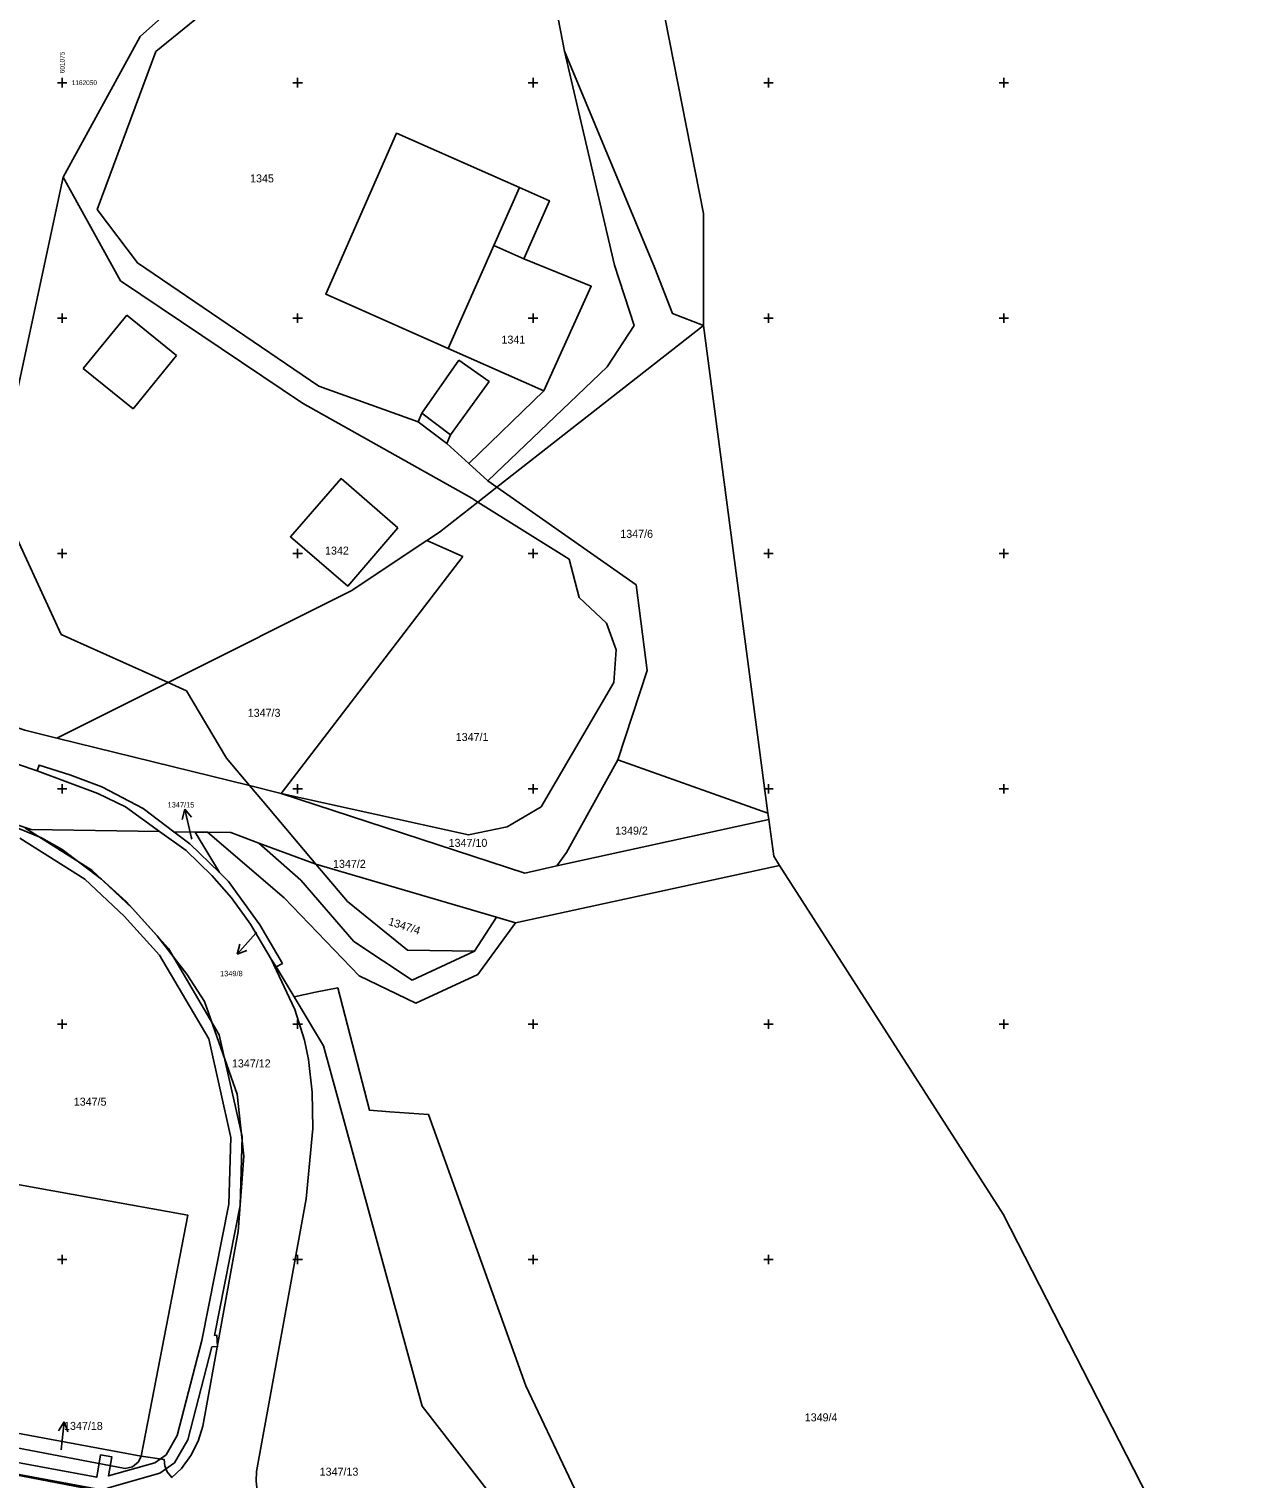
# Model space of a CAD drawing. Extents: x -601602 to -600882, y -1162594 to -1161950.
# Drawn here: x -601078.5 to -600948.1, y -1162198.3 to -1162044.3 of the extents above; entities that cross this region are included whole.
import ezdxf

# ---------------------------------------------------------------- set-up
doc = ezdxf.new("R2010")
doc.units = 0
for name, color, linetype in [('KN_Hranice parcel', 7, 'Continuous'), ('KN_Parcelní čísla', 7, 'Continuous'), ('KN_Pop  PČ popisy', 7, 'Continuous'), ('KN_Vnitřní kresba', 7, 'Continuous'), ('KN_Věcná břemena k části', 7, 'Continuous'), ('X_SOUR_KRIZKY_SEVER', 7, 'Continuous')]:
    doc.layers.add(name, color=color, linetype=linetype)

# ---------------------------------------------------------------- blocks, each defined once
blk = doc.blocks.new('1029_45')
at = {"layer": 'KN_Pop  PČ popisy'}
for p, q in [((0, 0), (-2.01, -2.23)), ((-2.01, -2.23), (-1.71, -1.15)), ((-2.01, -2.23), (-0.97, -1.82))]:
    blk.add_line(p, q, dxfattribs=at)
blk = doc.blocks.new('1029_48')
at = {"layer": 'KN_Pop  PČ popisy'}
for p, q in [((0.31, 2.98), (-0.29, 2.04)), ((0, 0), (0.31, 2.98)), ((0.31, 2.98), (0.71, 1.94))]:
    blk.add_line(p, q, dxfattribs=at)
blk = doc.blocks.new('1029_49')
at = {"layer": 'KN_Pop  PČ popisy'}
for p, q in [((-0.67, 2.92), (-0.94, 1.84)), ((0, 0), (-0.67, 2.92)), ((-0.67, 2.92), (0.04, 2.06))]:
    blk.add_line(p, q, dxfattribs=at)

msp = doc.modelspace()

# ---------------------------------------------------------------- linework, layer by layer
at = {"layer": 'KN_Hranice parcel'}
for p, q in [((-601006.89, -1162063.9), (-601012.85, -1162033.72)), ((-601006.89, -1162075.78), (-601006.89, -1162063.9)), ((-601028.83, -1162092.97), (-601006.89, -1162075.78)), ((-601000.04, -1162127.57), (-601006.89, -1162075.78)), ((-601030.85, -1162094.55), (-601028.83, -1162092.97)), ((-601028.83, -1162092.97), (-601014.03, -1162103.32)), ((-601075.13, -1162108.59), (-601081.23, -1162095.28)), ((-601034.94, -1162097.75), (-601030.85, -1162094.55)), ((-601021.16, -1162100.61), (-601030.85, -1162094.55)), ((-601036.27, -1162098.64), (-601034.94, -1162097.75)), ((-601044.3, -1162103.98), (-601036.27, -1162098.64)), ((-601036.27, -1162098.64), (-601032.45, -1162100.31)), ((-601032.45, -1162100.31), (-601051.74, -1162125.48)), ((-601063.76, -1162113.7), (-601044.3, -1162103.98)), ((-601063.76, -1162113.7), (-601075.13, -1162108.59)), ((-601075.58, -1162119.61), (-601063.76, -1162113.7)), ((-601015.98, -1162121.93), (-601021.44, -1162131.77)), ((-601015.98, -1162121.93), (-601000.04, -1162127.57)), ((-601066.42, -1162127.07), (-601063.14, -1162129.55)), ((-600999.94, -1162128.26), (-601000.04, -1162127.57)), ((-600999.94, -1162128.26), (-601022.46, -1162133.18)), ((-601063.14, -1162129.55), (-601060.89, -1162129.59)), ((-601060.89, -1162129.59), (-601059.59, -1162129.61)), ((-601060.89, -1162129.59), (-601058.31, -1162133.89)), ((-601059.59, -1162129.61), (-601051.43, -1162136.58)), ((-601021.44, -1162131.77), (-601022.46, -1162133.18)), ((-601026.86, -1162139.23), (-600998.81, -1162133.13)), ((-601058.31, -1162133.89), (-601057.34, -1162134.83)), ((-601030.85, -1162144.71), (-601026.86, -1162139.23)), ((-601052.29, -1162143.92), (-601052.8, -1162143.08)), ((-601052.29, -1162143.92), (-601051.55, -1162145.16)), ((-601051.55, -1162145.16), (-601050.38, -1162147.1)), ((-601050.38, -1162147.1), (-601048.11, -1162146.6)), ((-601081.71, -1162193.07), (-601066.62, -1162195.86))]:
    msp.add_line(p, q, dxfattribs=at)
for points in [[(-601074.92, -1162060.04), (-601066.73, -1162045.1), (-601055.5, -1162035.08), (-601053.32, -1162037.14), (-601024.32, -1162032.92)], [(-601024.32, -1162032.92), (-601021.67, -1162046.66), (-601012.07, -1162069.69), (-601010.2, -1162074.53), (-601006.89, -1162075.78)], [(-601025.96, -1162068.71), (-601023.26, -1162062.54), (-601026.43, -1162061.13), (-601039.49, -1162055.37), (-601047.02, -1162072.46), (-601034.01, -1162078.22)], [(-601081.23, -1162095.28), (-601079.76, -1162082.66), (-601074.92, -1162060.04)], [(-601034.01, -1162078.22), (-601023.86, -1162082.73), (-601018.82, -1162071.62), (-601025.96, -1162068.71)], [(-601039.35, -1162097.29), (-601045.39, -1162092.04), (-601050.77, -1162098.22), (-601044.66, -1162103.47), (-601039.35, -1162097.29)], [(-601051.74, -1162125.48), (-601031.84, -1162129.87), (-601027.76, -1162129.04), (-601024.13, -1162126.91), (-601016.43, -1162113.72), (-601016.17, -1162110.22), (-601017.21, -1162107.4), (-601020.09, -1162104.69), (-601021.16, -1162100.61)], [(-601014.03, -1162103.32), (-601012.86, -1162112.42), (-601015.98, -1162121.93)], [(-601092.4, -1162118.22), (-601089.49, -1162119.1), (-601077.68, -1162123.09)], [(-601084.43, -1162116.99), (-601078.97, -1162118.78), (-601075.58, -1162119.61)], [(-601051.74, -1162125.48), (-601055.11, -1162124.65), (-601075.58, -1162119.61)], [(-601077.68, -1162123.09), (-601077.46, -1162122.47), (-601074.19, -1162123.51), (-601070.78, -1162124.77), (-601066.42, -1162127.07)], [(-601092.71, -1162124.57), (-601078.32, -1162129.32), (-601064.66, -1162129.53)], [(-601064.66, -1162129.53), (-601068.3, -1162126.92), (-601071.21, -1162125.48), (-601077.68, -1162123.09)], [(-601066.62, -1162195.86), (-601064.16, -1162196.24), (-601064.09, -1162196.91), (-601063.85, -1162197.53), (-601063.36, -1162198.16), (-601062.35, -1162197.17), (-601061.34, -1162195.81), (-601060.57, -1162194.3), (-601060.06, -1162192.69), (-601056.32, -1162172.01), (-601055.73, -1162164.01), (-601056.42, -1162157.43), (-601059.89, -1162147.59), (-601061.76, -1162144.68), (-601064.91, -1162140.6), (-601068.2, -1162136.98), (-601070.82, -1162134.6), (-601075.02, -1162131.43), (-601077.22, -1162130.21), (-601079.54, -1162129.23), (-601092.67, -1162124.81)], [(-601022.46, -1162133.18), (-601025.87, -1162133.95), (-601051.74, -1162125.48)], [(-600998.81, -1162133.13), (-600999.43, -1162132.15), (-600999.94, -1162128.26)], [(-601052.8, -1162143.08), (-601055.02, -1162139.37), (-601057.04, -1162136.56), (-601059.11, -1162134.19), (-601061.84, -1162131.56), (-601064.66, -1162129.53)], [(-601063.14, -1162129.55), (-601061.44, -1162130.84), (-601058.31, -1162133.89)], [(-601059.59, -1162129.61), (-601057.11, -1162129.65), (-601054.11, -1162130.77), (-601048.07, -1162133.01), (-601028.89, -1162138.62), (-601026.86, -1162139.23)], [(-600948.1, -1162222.9), (-600975.07, -1162170.16), (-600998.81, -1162133.13)], [(-601057.34, -1162134.83), (-601054.01, -1162139.45), (-601051.61, -1162143.54), (-601052.29, -1162143.92)], [(-601051.43, -1162136.58), (-601043.47, -1162144.85), (-601037.45, -1162147.76), (-601030.85, -1162144.71)], [(-601013.57, -1162251.35), (-601016.12, -1162245.67), (-601024.4, -1162223.22), (-601026.53, -1162218.95), (-601028.43, -1162216.19), (-601030.73, -1162213.67), (-601033.66, -1162211.35), (-601038.51, -1162207.93), (-601040.83, -1162206.82), (-601045.14, -1162205.23), (-601049.69, -1162204.17), (-601051.26, -1162203.38), (-601052.26, -1162202.62), (-601053.7, -1162200.89), (-601054.31, -1162199.55), (-601054.41, -1162198.53), (-601054.37, -1162197.51), (-601049.08, -1162168.55), (-601048.4, -1162161.09), (-601048.45, -1162157.21), (-601048.83, -1162153.76), (-601049.27, -1162151.71), (-601050.29, -1162148.45), (-601052.8, -1162143.08)], [(-601048.11, -1162146.6), (-601045.74, -1162146.14), (-601042.38, -1162159.13), (-601040.21, -1162159.29), (-601036.1, -1162159.59), (-601025.77, -1162188.41), (-601016.62, -1162207.65), (-601008.28, -1162220.54), (-601006.06, -1162235.93), (-601008.31, -1162244.56), (-601009.56, -1162251.46), (-601010.04, -1162254.13)], [(-601012.29, -1162253.36), (-601022.17, -1162223.17), (-601028.08, -1162201.8), (-601036.78, -1162190.58), (-601047.27, -1162152.28), (-601050.38, -1162147.1)], [(-601066.62, -1162195.86), (-601065.25, -1162188.75), (-601061.68, -1162170.28), (-601086.05, -1162165.88)], [(-601081.49, -1162194.66), (-601068.33, -1162197.18), (-601067.54, -1162197), (-601066.91, -1162196.47), (-601066.62, -1162195.86)]]:
    msp.add_lwpolyline(points, dxfattribs=at)
at = {"layer": 'KN_Pop  PČ popisy'}
for p, q in [((-601061.25, -1162130.36), (-601061.32, -1162130.08)), ((-601054.35, -1162140.25), (-601054.43, -1162140.34))]:
    msp.add_line(p, q, dxfattribs=at)
at = {"layer": 'KN_Vnitřní kresba'}
for p, q in [((-601065.06, -1162046.67), (-601053.32, -1162037.14)), ((-601071.28, -1162063.47), (-601065.06, -1162046.67)), ((-601021.67, -1162046.66), (-601016.35, -1162069.39)), ((-601074.92, -1162060.04), (-601068.8, -1162071.03)), ((-601029.15, -1162067.28), (-601026.43, -1162061.13)), ((-601071.28, -1162063.47), (-601067.02, -1162069.14)), ((-601034.01, -1162078.22), (-601029.15, -1162067.28)), ((-601029.15, -1162067.28), (-601025.96, -1162068.71)), ((-601067.02, -1162069.14), (-601047.76, -1162082.22)), ((-601016.35, -1162069.39), (-601014.26, -1162075.79)), ((-601068.8, -1162071.03), (-601049.47, -1162084.03)), ((-601072.78, -1162080.36), (-601068.13, -1162074.68)), ((-601068.13, -1162074.68), (-601062.85, -1162078.98)), ((-601017.14, -1162080.19), (-601014.26, -1162075.79)), ((-601067.46, -1162084.65), (-601062.85, -1162078.98)), ((-601036.81, -1162085.11), (-601032.89, -1162079.46)), ((-601032.89, -1162079.46), (-601029.65, -1162081.73)), ((-601072.78, -1162080.36), (-601067.46, -1162084.65)), ((-601029.79, -1162092.29), (-601017.14, -1162080.19)), ((-601047.76, -1162082.22), (-601037.21, -1162086.03)), ((-601033.78, -1162087.39), (-601029.65, -1162081.73)), ((-601031.83, -1162090.43), (-601023.86, -1162082.73)), ((-601049.47, -1162084.03), (-601031.51, -1162094.11)), ((-601037.21, -1162086.03), (-601036.81, -1162085.11)), ((-601037.21, -1162086.03), (-601034.15, -1162088.32)), ((-601036.81, -1162085.11), (-601033.78, -1162087.39)), ((-601034.15, -1162088.32), (-601033.78, -1162087.39)), ((-601034.15, -1162088.32), (-601031.83, -1162090.43)), ((-601031.83, -1162090.43), (-601029.79, -1162092.29)), ((-601029.79, -1162092.29), (-601028.83, -1162092.97)), ((-601031.51, -1162094.11), (-601030.85, -1162094.55)), ((-601063.76, -1162113.7), (-601061.8, -1162114.58)), ((-601061.8, -1162114.58), (-601057.56, -1162121.73)), ((-601057.56, -1162121.73), (-601055.11, -1162124.65)), ((-601055.11, -1162124.65), (-601053.71, -1162126.32)), ((-601053.71, -1162126.32), (-601048.07, -1162133.01)), ((-601054.11, -1162130.77), (-601049.65, -1162134.69)), ((-601048.07, -1162133.01), (-601044.7, -1162136.95)), ((-601049.65, -1162134.69), (-601044.03, -1162141.2)), ((-601044.7, -1162136.95), (-601038.33, -1162142.13)), ((-601031.23, -1162142.24), (-601028.89, -1162138.62)), ((-601044.03, -1162141.2), (-601037.83, -1162145.33)), ((-601038.33, -1162142.13), (-601031.23, -1162142.24)), ((-601037.83, -1162145.33), (-601031.23, -1162142.24))]:
    msp.add_line(p, q, dxfattribs=at)
at = {"layer": 'KN_Věcná břemena k části'}
for points in [[(-601070.22, -1162199.27), (-601064.65, -1162197.68), (-601063.08, -1162196.58), (-601061.67, -1162194.15), (-601059.1, -1162184.28), (-601058.5, -1162184.24), (-601058.58, -1162183.04), (-601058.84, -1162183.06), (-601056.11, -1162169.24), (-601055.88, -1162161.91), (-601058.32, -1162151.12), (-601063.7, -1162141.94), (-601067.56, -1162137.69), (-601071.86, -1162133.64), (-601078.97, -1162129.14)], [(-601079.49, -1162130.24), (-601072.6, -1162134.6), (-601068.42, -1162138.53), (-601064.68, -1162142.66), (-601059.44, -1162151.56), (-601057.08, -1162162.03), (-601057.31, -1162169.1), (-601060.17, -1162183.58), (-601062.79, -1162193.69), (-601063.98, -1162195.74), (-601065.17, -1162196.58), (-601070.1, -1162197.98), (-601069.75, -1162195.94), (-601070.93, -1162195.74), (-601071.33, -1162198.12), (-601081.27, -1162196.27)], [(-601064.31, -1162200.86), (-601081.08, -1162197.65), (-601109.56, -1162192.2), (-601128.66, -1162188.54), (-601200.82, -1162175.41), (-601199.01, -1162172.46), (-601202.48, -1162171.8), (-601204.29, -1162174.75), (-601231.79, -1162169.15), (-601243.26, -1162166.79), (-601243.86, -1162170.07), (-601234.04, -1162172.11), (-601234.97, -1162177.31), (-601231.73, -1162177.92), (-601230.82, -1162172.83), (-601203.86, -1162178.32), (-601130.82, -1162191.5), (-601132.08, -1162200.52)], [(-601081.1, -1162197.53), (-601071.41, -1162199.33)]]:
    msp.add_lwpolyline(points, dxfattribs=at)
at = {"layer": 'X_SOUR_KRIZKY_SEVER'}
for p, q in [((-601075.5, -1162050), (-601074.5, -1162050)), ((-601075, -1162050.5), (-601075, -1162049.5)), ((-601050.5, -1162050), (-601049.5, -1162050)), ((-601050, -1162050.5), (-601050, -1162049.5)), ((-601025.5, -1162050), (-601024.5, -1162050)), ((-601025, -1162050.5), (-601025, -1162049.5)), ((-601000.5, -1162050), (-600999.5, -1162050)), ((-601000, -1162050.5), (-601000, -1162049.5)), ((-600975.5, -1162050), (-600974.5, -1162050)), ((-600975, -1162050.5), (-600975, -1162049.5)), ((-601075.5, -1162075), (-601074.5, -1162075)), ((-601075, -1162075.5), (-601075, -1162074.5)), ((-601050.5, -1162075), (-601049.5, -1162075)), ((-601050, -1162075.5), (-601050, -1162074.5)), ((-601025.5, -1162075), (-601024.5, -1162075)), ((-601025, -1162075.5), (-601025, -1162074.5)), ((-601000.5, -1162075), (-600999.5, -1162075)), ((-601000, -1162075.5), (-601000, -1162074.5)), ((-600975.5, -1162075), (-600974.5, -1162075)), ((-600975, -1162075.5), (-600975, -1162074.5)), ((-601075, -1162100.5), (-601075, -1162099.5)), ((-601050, -1162100.5), (-601050, -1162099.5)), ((-601025, -1162100.5), (-601025, -1162099.5)), ((-601000, -1162100.5), (-601000, -1162099.5)), ((-600975, -1162100.5), (-600975, -1162099.5)), ((-601075.5, -1162100), (-601074.5, -1162100)), ((-601050.5, -1162100), (-601049.5, -1162100)), ((-601025.5, -1162100), (-601024.5, -1162100)), ((-601000.5, -1162100), (-600999.5, -1162100)), ((-600975.5, -1162100), (-600974.5, -1162100)), ((-601075, -1162125.5), (-601075, -1162124.5)), ((-601050, -1162125.5), (-601050, -1162124.5)), ((-601025, -1162125.5), (-601025, -1162124.5)), ((-601000, -1162125.5), (-601000, -1162124.5)), ((-600975, -1162125.5), (-600975, -1162124.5)), ((-601075.5, -1162125), (-601074.5, -1162125)), ((-601050.5, -1162125), (-601049.5, -1162125)), ((-601025.5, -1162125), (-601024.5, -1162125)), ((-601000.5, -1162125), (-600999.5, -1162125)), ((-600975.5, -1162125), (-600974.5, -1162125)), ((-601075.5, -1162150), (-601074.5, -1162150)), ((-601075, -1162150.5), (-601075, -1162149.5)), ((-601050.5, -1162150), (-601049.5, -1162150)), ((-601050, -1162150.5), (-601050, -1162149.5)), ((-601025.5, -1162150), (-601024.5, -1162150)), ((-601025, -1162150.5), (-601025, -1162149.5)), ((-601000.5, -1162150), (-600999.5, -1162150)), ((-601000, -1162150.5), (-601000, -1162149.5)), ((-600975.5, -1162150), (-600974.5, -1162150)), ((-600975, -1162150.5), (-600975, -1162149.5)), ((-601075.5, -1162175), (-601074.5, -1162175)), ((-601075, -1162175.5), (-601075, -1162174.5)), ((-601050.5, -1162175), (-601049.5, -1162175)), ((-601050, -1162175.5), (-601050, -1162174.5)), ((-601025.5, -1162175), (-601024.5, -1162175)), ((-601025, -1162175.5), (-601025, -1162174.5)), ((-601000.5, -1162175), (-600999.5, -1162175)), ((-601000, -1162175.5), (-601000, -1162174.5))]:
    msp.add_line(p, q, dxfattribs=at)

# ---------------------------------------------------------------- block references
at = {"layer": 'KN_Pop  PČ popisy'}
for name, p in [('1029_49', (-601061.32, -1162130.08)), ('1029_45', (-601054.43, -1162140.34)), ('1029_48', (-601075.12, -1162195.22))]:
    msp.add_blockref(name, p, dxfattribs=at)

# ---------------------------------------------------------------- texts
at = {"layer": 'KN_Parcelní čísla'}
for s, height, p in [('1345', 0.85, (-601055.05, -1162060.59)), ('1341', 0.85, (-601028.35, -1162077.71)), ('1347/6', 0.85, (-601015.73, -1162098.34)), ('1342', 0.85, (-601047.09, -1162100.12)), ('1347/3', 0.85, (-601055.3, -1162117.35)), ('1347/1', 0.85, (-601033.21, -1162119.92)), ('1347/15', 0.569, (-601063.81, -1162126.98)), ('1349/2', 0.85, (-601016.28, -1162129.86)), ('1347/10', 0.85, (-601033.96, -1162131.16)), ('1347/2', 0.85, (-601046.24, -1162133.39)), ('1349/8', 0.569, (-601058.24, -1162144.9)), ('1347/12', 0.85, (-601056.98, -1162154.59)), ('1347/5', 0.85, (-601073.78, -1162158.65)), ('1347/18', 0.85, (-601074.81, -1162193.09)), ('1349/4', 0.85, (-600996.14, -1162192.18)), ('1347/13', 0.85, (-601047.66, -1162197.95))]:
    msp.add_text(s, height=height, dxfattribs=at).set_placement(p)
msp.add_text('1347/4', height=0.85, rotation=342, dxfattribs=at).set_placement((-601040.44, -1162139.43))
at = {"layer": 'X_SOUR_KRIZKY_SEVER'}
msp.add_text('601075', height=0.5, rotation=90, dxfattribs=at).set_placement((-601074.75, -1162049))
msp.add_text('1162050', height=0.5, dxfattribs=at).set_placement((-601074, -1162050.25))

doc.saveas('drawing.dxf')
